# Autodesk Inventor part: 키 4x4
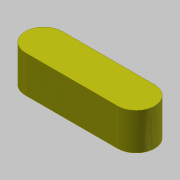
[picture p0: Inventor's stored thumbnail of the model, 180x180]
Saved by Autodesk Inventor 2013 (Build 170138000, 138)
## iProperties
Created: 2018-09
Part Number: 키 4x4
Document SubType Name: Modeling
Density: 1 g/cm^3
Material: 강철, 연강
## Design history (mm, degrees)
sketch "스케치1"
  geometry: L1 (-5, -2)-(5, -2); L2 (5, 2)-(-5, 2); A1 r 2 centre (5, 0) between (5, -2) and (5, 2); A2 r 2 centre (-5, 0) between (-5, 2) and (-5, -2); 2 further points
  constraints: 4 end point, 4 point on circle, 4 tangent, 2 centre point, 1 horizontal, 1 horizontal alignment, 1 midpoint, 1 parallel, 1 vertical alignment
  dimensions: "d0" = 4 distance between parallel lines of L1 L2; "d1" = 14 dimension on A1 A2
extrude "돌출1" new body sketch "스케치1" stored distance "d2" = 4; taper "d3" = 0 deg
node "솔리드1"
